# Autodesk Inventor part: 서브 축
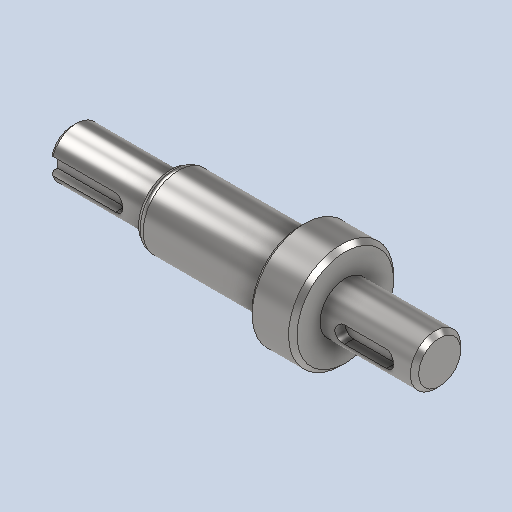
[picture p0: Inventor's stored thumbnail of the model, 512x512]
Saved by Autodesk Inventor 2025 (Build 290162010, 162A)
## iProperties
Created: 2024-07
Part Number: 서브 축
Material: 강철, 연강
Document SubType Name: Modeling
Designer: 학생
Density: 7.86 g/cm^3
Appearance: 기본값
Author: jhkim
Revision Number: 1
Sending System: Autodesk Inventor 2025
Preprocessor: ST-DEVELOPER v20
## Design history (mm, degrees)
feature "솔리드1"
node "솔리드2"
